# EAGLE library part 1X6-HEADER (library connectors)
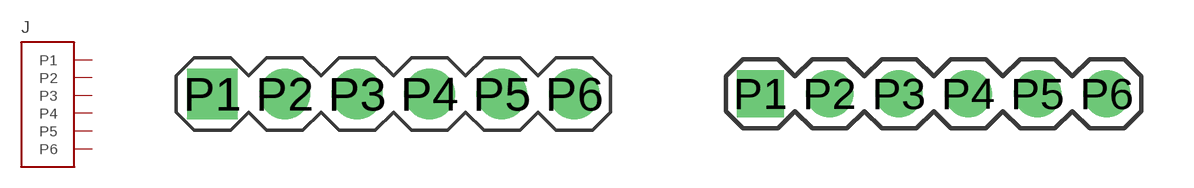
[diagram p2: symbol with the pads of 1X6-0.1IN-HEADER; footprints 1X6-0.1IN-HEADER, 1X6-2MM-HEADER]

Designator prefix J

## 1X6-HEADER0.1IN  [1X6-0.1IN-HEADER]
P1  P1  pas
P2  P2  pas
P3  P3  pas
P4  P4  pas
P5  P5  pas
P6  P6  pas

## 1X6-HEADER2MM  [1X6-2MM-HEADER]
Pads as for 1X6-0.1IN-HEADER

## Footprint 1X6-0.1IN-HEADER (pad centres in mm)
drill 1.05 pad 1.778 square: P1 -6.35,0
drill 1.05 pad 1.778 round: P2 -3.81,0; P3 -1.27,0; P4 1.27,0; P5 3.81,0; P6 6.35,0

## Footprint 1X6-2MM-HEADER (pad centres in mm)
drill 0.85 square: P1 -5,0
drill 0.85 round: P2 -3,0; P3 -1,0; P4 1,0; P5 3,0; P6 5,0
